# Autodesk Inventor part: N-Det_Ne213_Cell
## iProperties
Shininess: 64.0
Length Units: 11269
Angle Units: 11279
Time Units: 11290
Mass Units: 11283
Length Display Precision: 3
Angle Display Precision: 2
Compacted: True
Part Number: N-Det_Ne213_Cell
Document SubType Name: Modeling
Created: 2005-04
Designer: John Blackburn
Manufacturer: Standard
Standards Organization: Custom
Density: 0.0
Volumn: 0.0
Area: 0.0
PropertySet Name: Model Information
Control State: 0
Master: False
Checked Out: False
Author: John Blackburn
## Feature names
1. Extrusion1
